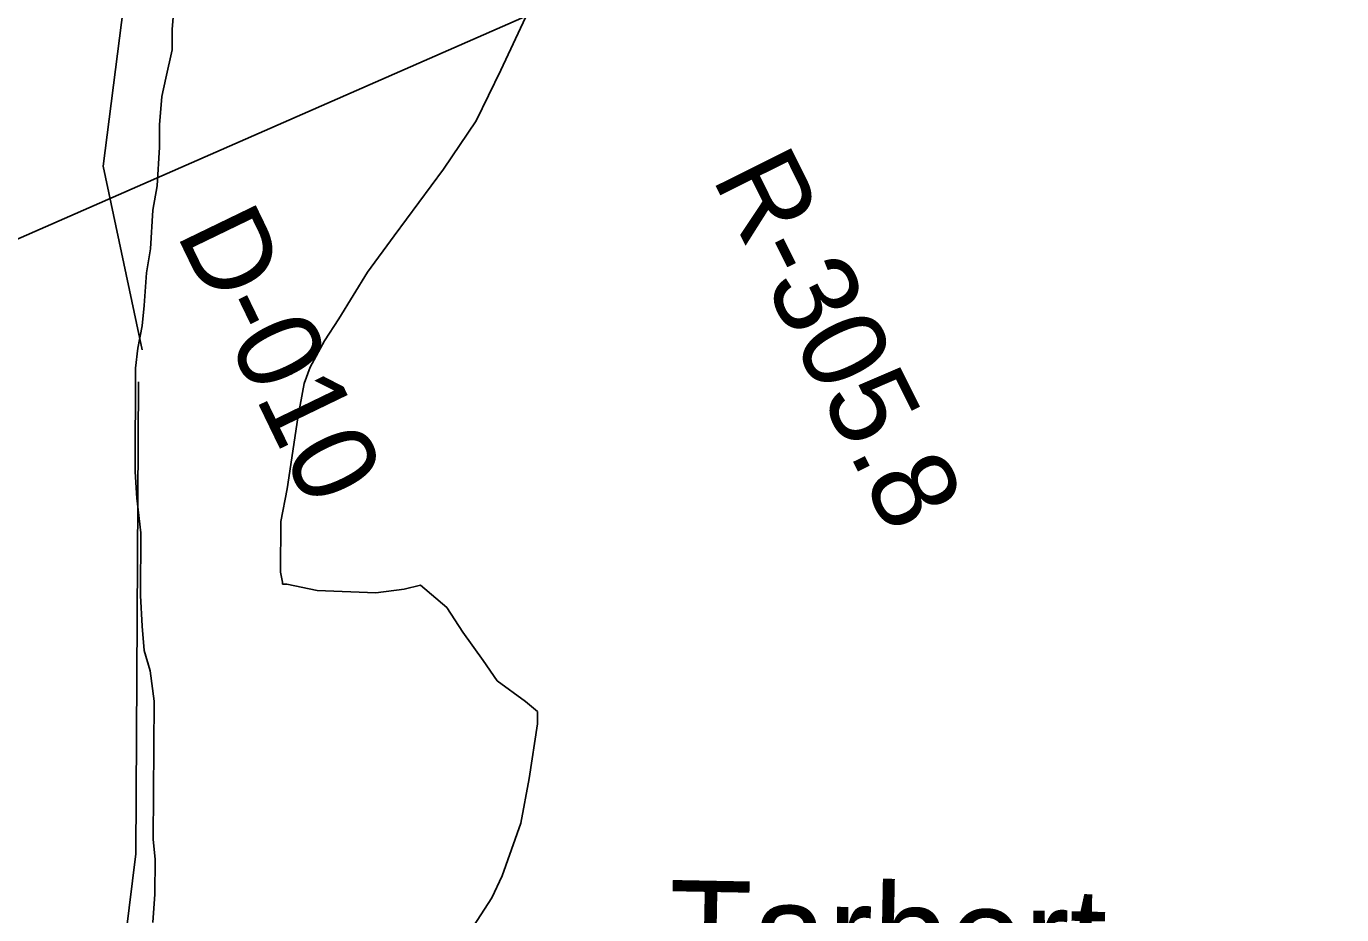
# Model space of a CAD drawing. Extents: x 3177385 to 3215275, y 903885 to 929304.
# Drawn here: x 3199163 to 3200457, y 912486 to 913360 of the extents above; entities that cross this region are included whole.
import ezdxf

# ---------------------------------------------------------------- set-up
doc = ezdxf.new("R2010")
doc.units = 0
for name, color, linetype in [('V-RIVR-RANG-IDEN', 7, 'Continuous'), ('V-SITE-VEGE', 7, 'Continuous'), ('V-TOPO-BNDY', 7, 'Continuous'), ('V-TOPO-GNAM-IDEN', 7, 'Continuous'), ('V-TOPO-SHOR', 7, 'Continuous')]:
    doc.layers.add(name, color=color, linetype=linetype)

msp = doc.modelspace()

# ---------------------------------------------------------------- linework, layer by layer
at = {"layer": 'V-SITE-VEGE'}
for p, q in [((3199306.4, 913356.6), (3199308.6, 913384.6)), ((3199306.3, 913336.7), (3199306.4, 913356.6)), ((3199653.9, 913368.6), (3199629.7, 913316.8)), ((3199300.1, 913308.8), (3199306.3, 913336.7)), ((3199296.1, 913290.8), (3199300.1, 913308.8)), ((3199629.7, 913316.8), (3199605.4, 913267)), ((3199293.9, 913262.9), (3199296.1, 913290.8)), ((3199605.4, 913267), (3199573.2, 913219.3)), ((3199293.8, 913240.9), (3199293.9, 913262.9)), ((3199291.5, 913203), (3199293.8, 913240.9)), ((3199573.2, 913219.3), (3199524.9, 913153.7)), ((3199287.4, 913179), (3199291.5, 913203)), ((3199285.2, 913141.1), (3199287.4, 913179)), ((3199524.9, 913153.7), (3199498.7, 913117.9)), ((3199281.1, 913117.2), (3199285.2, 913141.1)), ((3199278.9, 913085.2), (3199281.1, 913117.2)), ((3199498.7, 913117.9), (3199470.5, 913072.1)), ((3199276.8, 913065.3), (3199278.9, 913085.2)), ((3199470.5, 913072.1), (3199456.4, 913050.3)), ((3199272.6, 913043.3), (3199276.8, 913065.3)), ((3199456.4, 913050.3), (3199442.3, 913024.4)), ((3199270.5, 913023.4), (3199272.6, 913043.3)), ((3199269.9, 912921.6), (3199270.5, 913023.4)), ((3199442.3, 913024.4), (3199436.2, 913008.5)), ((3199436.2, 913008.5), (3199430, 912974.5)), ((3199430, 912974.5), (3199419.6, 912904.7)), ((3199271.8, 912895.6), (3199269.9, 912921.6)), ((3199419.6, 912904.7), (3199413.4, 912872.8)), ((3199275.6, 912861.6), (3199271.8, 912895.6)), ((3199413.4, 912872.8), (3199413.1, 912822.9)), ((3199275.2, 912799.7), (3199275.6, 912861.6)), ((3199413.1, 912822.9), (3199415.1, 912812.9)), ((3199415.1, 912812.9), (3199415.1, 912810.9)), ((3199415.1, 912810.9), (3199419.1, 912810.9)), ((3199419.1, 912810.9), (3199449, 912804.7)), ((3199449, 912804.7), (3199506.9, 912802.4)), ((3199506.9, 912802.4), (3199534.8, 912806.2)), ((3199534.8, 912806.2), (3199550.8, 912810.1)), ((3199550.8, 912810.1), (3199576.7, 912788)), ((3199277, 912769.8), (3199275.2, 912799.7)), ((3199576.7, 912788), (3199592.5, 912763.9)), ((3199278.9, 912745.8), (3199277, 912769.8)), ((3199592.5, 912763.9), (3199612.3, 912735.9)), ((3199284.8, 912725.8), (3199278.9, 912745.8)), ((3199612.3, 912735.9), (3199626.2, 912715.8)), ((3199288.6, 912695.8), (3199284.8, 912725.8)), ((3199626.2, 912715.8), (3199654, 912695.7)), ((3199287.8, 912560.1), (3199288.6, 912695.8)), ((3199654, 912695.7), (3199665.9, 912685.6)), ((3199665.9, 912685.6), (3199665.8, 912673.7)), ((3199665.8, 912673.7), (3199657.5, 912619.8)), ((3199657.5, 912619.8), (3199649.3, 912575.9)), ((3199649.3, 912575.9), (3199631, 912524.1)), ((3199289.7, 912540.1), (3199287.8, 912560.1)), ((3199289.5, 912506.1), (3199289.7, 912540.1)), ((3199631, 912524.1), (3199620.9, 912502.2)), ((3199287.3, 912478.2), (3199289.5, 912506.1)), ((3199620.9, 912502.2), (3199602.8, 912474.4))]:
    msp.add_line(p, q, dxfattribs=at)
at = {"layer": 'V-TOPO-BNDY'}
msp.add_lwpolyline([(3212104.8, 927455), (3211654.7, 925302.3), (3210557.1, 922651.3), (3209209.3, 920082.8), (3207894, 918536.9), (3206269, 917198.2), (3204190, 915875.2), (3202489, 914709.7), (3200914, 913922.2), (3198614.5, 912914.1), (3196094.5, 911748.6), (3194267.5, 911118.6), (3192913, 910488.6), (3191155.6, 909558.2), (3212939.7, 909531.5)], dxfattribs=at)
at = {"layer": 'V-TOPO-SHOR'}
for points in [[(3199277, 913041.5), (3199238.4, 913222.2), (3199292.5, 913646.8)], [(3198619, 911410.6), (3198867.4, 911403.7), (3198973, 911424.9), (3199291.5, 911535.2), (3199263, 911879.6), (3199225.1, 912176.4), (3199270.7, 912545.7), (3199273.2, 913010.1)]]:
    msp.add_lwpolyline(points, dxfattribs=at)

# ---------------------------------------------------------------- texts
at = {"layer": 'V-RIVR-RANG-IDEN'}
for s, rotation, p in [('R-305.8', 296.4855, (3199837, 913211)), ('D-010', 295.8247, (3199310, 913155.9))]:
    msp.add_text(s, height=83, rotation=rotation, dxfattribs=at).set_placement(p)
at = {"layer": 'V-TOPO-GNAM-IDEN'}
msp.add_text('Tarbert', height=100, rotation=358.886, dxfattribs=at).set_placement((3199794, 912420))

doc.saveas('drawing.dxf')
